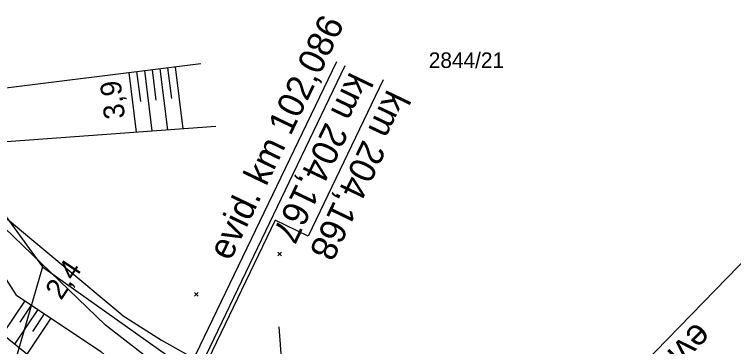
# Model space of a CAD drawing. Extents: x -800194 to -799078, y -1007177 to -1006597.
# Drawn here: x -799787.9 to -799718.7, y -1006945.4 to -1006913.4 of the extents above; entities that cross this region are included whole.
import ezdxf

# ---------------------------------------------------------------- set-up
doc = ezdxf.new("R2010")
doc.units = 0
for name, color, linetype in [('02_Osa_koleje', 7, 'Continuous'), ('Vrstva 17', 7, 'Continuous'), ('Vrstva 18', 7, 'Continuous'), ('Vrstva 2', 7, 'Continuous'), ('Vrstva 3', 7, 'Continuous'), ('Vrstva 48', 7, 'Continuous'), ('Vrstva 49', 7, 'Continuous'), ('Vrstva 55', 7, 'Continuous'), ('Vrstva 57', 7, 'Continuous'), ('Vrstva 6', 7, 'Continuous')]:
    doc.layers.add(name, color=color, linetype=linetype)

msp = doc.modelspace()

# ---------------------------------------------------------------- linework, layer by layer
at = {"layer": '02_Osa_koleje'}
msp.add_arc((-799651.022, -1006703.891), 292, 255.62486, 308.20516, dxfattribs=at)
at = {"layer": 'Vrstva 17'}
msp.add_lwpolyline([(-799756.721, -1006963.941), (-799759.125, -1006956.836), (-799761.008, -1006952.49), (-799761.962, -1006949.962), (-799762.434, -1006943.507)], dxfattribs=at)
at = {"layer": 'Vrstva 18'}
msp.add_line((-799754.68, -1006975.182), (-799715.262, -1006934.616), dxfattribs=at)
at = {"layer": 'Vrstva 2'}
msp.add_line((-799756.904, -1006917.966), (-799780.025, -1006965.993), dxfattribs=at)
at = {"layer": 'Vrstva 3'}
msp.add_line((-799756.121, -1006918.343), (-799779.128, -1006966.408), dxfattribs=at)
at = {"layer": 'Vrstva 48'}
for p, q in [((-799776.898, -1006919.002), (-799776.188, -1006924.741)), ((-799776.153, -1006918.91), (-799775.796, -1006921.798)), ((-799775.409, -1006918.818), (-799774.69, -1006924.632)), ((-799774.665, -1006918.726), (-799774.303, -1006921.651)), ((-799773.92, -1006918.633), (-799773.192, -1006924.523)), ((-799773.176, -1006918.541), (-799772.809, -1006921.505)), ((-799772.432, -1006918.449), (-799771.694, -1006924.413)), ((-799786.921, -1006940.996), (-799789.081, -1006944.231)), ((-799785.673, -1006941.829), (-799787.91, -1006945.178)), ((-799786.297, -1006941.412), (-799787.396, -1006943.059)), ((-799785.05, -1006942.245), (-799786.187, -1006943.948)), ((-799784.426, -1006942.662), (-799786.738, -1006946.125))]:
    msp.add_line(p, q, dxfattribs=at)
at = {"layer": 'Vrstva 49'}
for p, q in [((-799796.895, -1006926.253), (-799768.526, -1006924.182)), ((-799787.714, -1006940.466), (-799796.895, -1006926.253)), ((-799777.554, -1006942.387), (-799796.895, -1006926.253)), ((-799762.55, -1006936.32), (-799762.196, -1006936.674)), ((-799762.55, -1006936.674), (-799762.196, -1006936.32)), ((-799770.589, -1006940.179), (-799770.235, -1006940.533)), ((-799770.589, -1006940.533), (-799770.235, -1006940.179))]:
    msp.add_line(p, q, dxfattribs=at)
for points in [[(-799779.16, -1006943.327), (-799796.895, -1006926.253), (-799814.584, -1006901.56)], [(-799796.895, -1006926.253), (-799791.85, -1006920.852), (-799769.973, -1006918.145)], [(-799783.829, -1006948.476), (-799791.557, -1006942.231), (-799800.207, -1006931.486), (-799804.329, -1006925.793)], [(-799787.714, -1006940.466), (-799779.601, -1006945.884), (-799774.772, -1006950.23), (-799772.678, -1006954.259), (-799772.914, -1006957.256), (-799775.374, -1006960.084), (-799777.823, -1006961.225), (-799780.709, -1006960.303)], [(-799777.554, -1006942.387), (-799773.745, -1006944.786), (-799766.953, -1006948.615), (-799760.613, -1006955.042), (-799758.076, -1006961.72), (-799756.886, -1006965.592)], [(-799760.173, -1006964.364), (-799762.769, -1006960.758), (-799769.93, -1006954.183), (-799773.856, -1006947.464), (-799779.16, -1006943.327)]]:
    msp.add_lwpolyline(points, dxfattribs=at)
at = {"layer": 'Vrstva 55'}
msp.add_line((-799785.23, -1006937.71), (-799741.57, -1006968.68), dxfattribs=at)
for points in [[(-799815.49, -1006895.78), (-799807.53, -1006905.17), (-799803.4, -1006912.69), (-799785.23, -1006937.71)], [(-799785.23, -1006937.71), (-799791.69, -1006959.99), (-799791.97, -1006960.97), (-799746.76, -1006987.67), (-799745.68, -1006988.03), (-799733.28, -1006992.13)]]:
    msp.add_lwpolyline(points, dxfattribs=at)
at = {"layer": 'Vrstva 6'}
msp.add_lwpolyline([(-799752.416, -1006919.71), (-799759.639, -1006934.751), (-799762.823, -1006933.223), (-799777.74, -1006964.286)], dxfattribs=at)

# ---------------------------------------------------------------- texts
at = {"layer": 'Vrstva 18'}
msp.add_text('evid. km 204,200', height=2.5, rotation=225.63575, dxfattribs=at).set_placement((-799722.248, -1006942.945))
at = {"layer": 'Vrstva 2'}
msp.add_text('evid. km 102,086', height=2.5, rotation=64.34886, dxfattribs=at).set_placement((-799767.141, -1006937.24))
at = {"layer": 'Vrstva 3'}
msp.add_text('km 204,167', height=2.5, rotation=244.42082, dxfattribs=at).set_placement((-799755.61, -1006918.831))
at = {"layer": 'Vrstva 48'}
for s, rotation, p in [('3,9', 97.05377, (-799777.256, -1006923.37)), ('2,4', 56.26432, (-799783.421, -1006941.016))]:
    msp.add_text(s, height=2, rotation=rotation, dxfattribs=at).set_placement(p)
at = {"layer": 'Vrstva 57'}
msp.add_text('2844/21', height=1.5, dxfattribs=at).set_placement((-799748.03, -1006918.56))
at = {"layer": 'Vrstva 6'}
msp.add_text('km 204,168', height=2.5, rotation=244.34847, dxfattribs=at).set_placement((-799752.001, -1006920.52))

doc.saveas('drawing.dxf')
